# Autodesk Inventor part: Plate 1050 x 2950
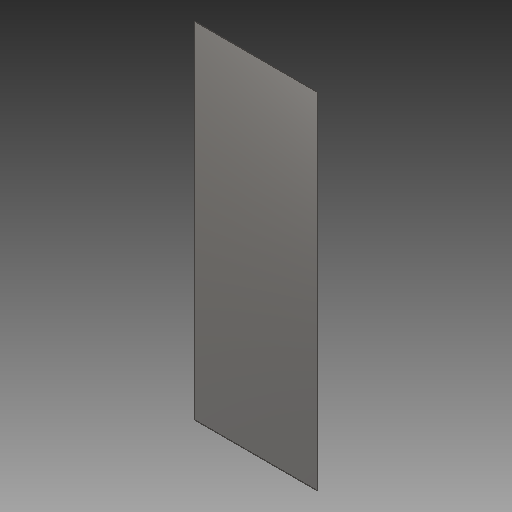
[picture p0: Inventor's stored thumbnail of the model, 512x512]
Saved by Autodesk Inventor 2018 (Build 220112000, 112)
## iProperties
Created: 2020-10
Part Number: Plate 1050 x 2950
Material: Steel, Mild
Document SubType Name: Modeling
Designer: cadcr
Density: 7.85 g/cm^3
Appearance: Semi-Polished
Author: cadcr
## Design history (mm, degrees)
sketch "Sketch1"
  geometry: L1 (-525, -1475)-(525, -1475); L2 (525, -1475)-(525, 1475); L3 (525, 1475)-(-525, 1475); L4 (-525, 1475)-(-525, -1475); L5 (-525, -1475)-(525, 1475); L6 (525, -1475)-(-525, 1475); 1 further point
  constraints: 12 end point, 2 midpoint, 2 parallel, 1 horizontal, 1 perpendicular
  dimensions: "d0" = 1050 distance of L2.end L3.end; "d1" = 2950 distance of L1.end L2.end
extrude "Extrusion1" new body sketch "Sketch1" distance "d2" = 3; taper "d3" = 0 deg
body "Solid1"
